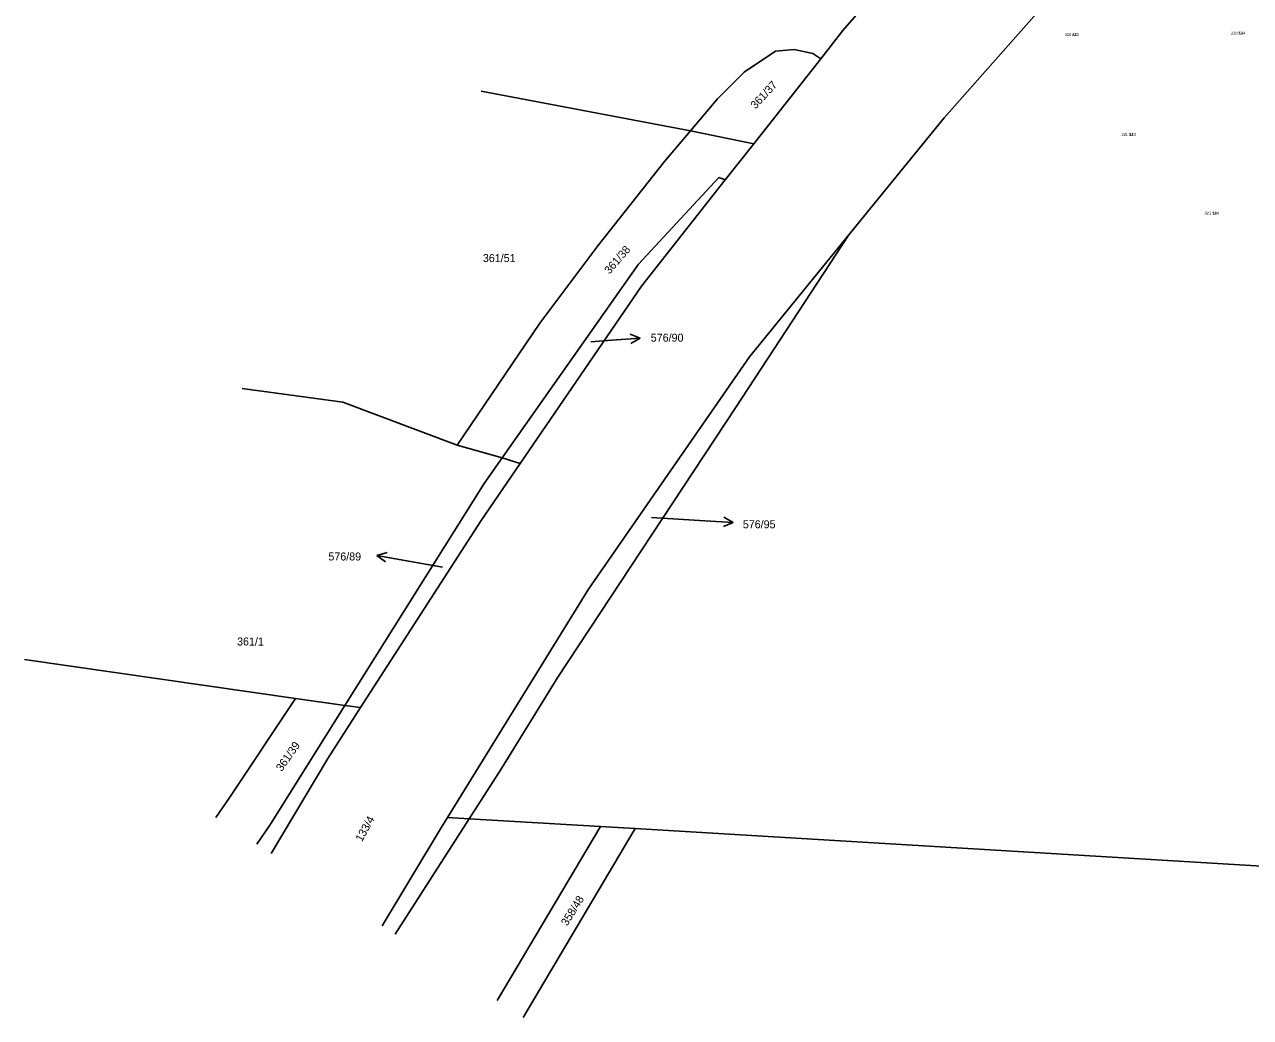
# Model space of a CAD drawing. Extents: x -742884 to -742543, y -1054677 to -1054433.
# Drawn here: x -742884.1 to -742753.9, y -1054651.8 to -1054546.4 of the extents above; entities that cross this region are included whole.
import ezdxf

# ---------------------------------------------------------------- set-up
doc = ezdxf.new("R2010")
doc.units = 0
for name, color, linetype in [('Vrstva 1', 7, 'Continuous'), ('Vrstva 11', 7, 'Continuous'), ('Vrstva 2', 7, 'Continuous'), ('Vrstva 3', 7, 'Continuous'), ('Vrstva 50', 7, 'Continuous')]:
    doc.layers.add(name, color=color, linetype=linetype)

msp = doc.modelspace()

# ---------------------------------------------------------------- linework, layer by layer
at = {"layer": 'Vrstva 1'}
for p, q in [((-742772.8, -1054547.58), (-742772.8, -1054547.58)), ((-742755.15, -1054547.44), (-742755.15, -1054547.44)), ((-742766.77, -1054558.2), (-742766.77, -1054558.2)), ((-742757.95, -1054566.55), (-742757.95, -1054566.55))]:
    msp.add_line(p, q, dxfattribs=at)
at = {"layer": 'Vrstva 11'}
msp.add_spline([(-742641.45, -1054542), (-742646.08, -1054542.32), (-742650.28, -1054545.1), (-742653.63, -1054549.14), (-742658.66, -1054557.13), (-742664.13, -1054565.84), (-742667.81, -1054569.62), (-742669.76, -1054570.07), (-742674.4, -1054567.88), (-742684.66, -1054562.03), (-742693.02, -1054556.88), (-742694.43, -1054554.37), (-742693.99, -1054552.67), (-742684.52, -1054539.64), (-742677.51, -1054529.95), (-742676.26, -1054526.54), (-742677.27, -1054522.39), (-742681.19, -1054517.29), (-742689.28, -1054510.73), (-742697.86, -1054505.14), (-742704.02, -1054502.75), (-742713.11, -1054501.07), (-742723.98, -1054503.51), (-742736.77, -1054510.1), (-742745.39, -1054515.75), (-742752.81, -1054521.82), (-742762.72, -1054531.38), (-742770.54, -1054539.36), (-742775.54, -1054544.64)], degree=3, dxfattribs=at)
at = {"layer": 'Vrstva 50'}
for p, q in [((-742806.65, -1054559.03), (-742799.53, -1054550)), ((-742810.52, -1054554.25), (-742813.37, -1054557.65)), ((-742813.37, -1054557.65), (-742816.15, -1054560.93)), ((-742813.37, -1054557.65), (-742806.65, -1054559.03)), ((-742809.68, -1054562.87), (-742806.65, -1054559.03)), ((-742829.38, -1054578.09), (-742838.16, -1054591.04)), ((-742821.73, -1054579.9), (-742818.74, -1054579.69)), ((-742818.74, -1054579.69), (-742819.77, -1054579.26)), ((-742818.74, -1054579.69), (-742819.7, -1054580.26)), ((-742823.97, -1054580.07), (-742821.73, -1054579.9)), ((-742833.37, -1054592.38), (-742838.16, -1054591.04)), ((-742831.46, -1054592.98), (-742833.37, -1054592.38)), ((-742817.51, -1054598.74), (-742811.86, -1054599.08)), ((-742811.86, -1054599.08), (-742808.86, -1054599.24)), ((-742808.86, -1054599.24), (-742809.89, -1054599.69)), ((-742808.86, -1054599.24), (-742809.84, -1054598.69)), ((-742846.68, -1054602.77), (-742845.6, -1054602.45)), ((-742843.72, -1054603.29), (-742846.68, -1054602.77)), ((-742846.68, -1054602.77), (-742845.78, -1054603.44)), ((-742839.71, -1054603.99), (-742843.72, -1054603.29)), ((-742855.32, -1054617.94), (-742850.08, -1054618.69)), ((-742848.43, -1054618.92), (-742850.08, -1054618.69)), ((-742839.19, -1054630.57), (-742836.88, -1054630.71)), ((-742822.95, -1054631.55), (-742836.88, -1054630.71)), ((-742833.92, -1054650.02), (-742822.95, -1054631.55)), ((-742819.25, -1054631.77), (-742831.15, -1054651.82)), ((-742819.25, -1054631.77), (-742822.95, -1054631.55)), ((-742684.03, -1054639.89), (-742819.25, -1054631.77))]:
    msp.add_line(p, q, dxfattribs=at)
for points in [[(-742724.95, -1054484.46), (-742747.39, -1054511.11), (-742766.3, -1054533.47), (-742786.45, -1054556.28), (-742796.57, -1054568.72)], [(-742799.53, -1054550), (-742797.18, -1054547.02), (-742783.25, -1054530.97)], [(-742799.53, -1054550), (-742800.38, -1054549.44), (-742802.37, -1054549.04), (-742804.34, -1054549.2), (-742807.67, -1054551.44), (-742810.52, -1054554.25)], [(-742813.37, -1054557.65), (-742835.62, -1054553.44)], [(-742816.15, -1054560.93), (-742823.22, -1054569.87), (-742829.38, -1054578.09)], [(-742833.37, -1054592.38), (-742818.9, -1054571.81), (-742810.36, -1054562.62), (-742809.68, -1054562.87)], [(-742831.46, -1054592.98), (-742818.59, -1054574.17), (-742809.68, -1054562.87)], [(-742796.57, -1054568.72), (-742807.1, -1054581.66), (-742824.22, -1054606.33), (-742839.19, -1054630.57)], [(-742796.57, -1054568.72), (-742808.61, -1054587.07), (-742827.46, -1054615.67), (-742833.45, -1054625.38), (-742836.88, -1054630.71)], [(-742838.16, -1054591.04), (-742850.31, -1054586.48), (-742860.99, -1054585.01)], [(-742850.08, -1054618.69), (-742835.29, -1054595.11), (-742833.37, -1054592.38)], [(-742848.43, -1054618.92), (-742835.61, -1054599.05), (-742831.46, -1054592.98)], [(-742884.11, -1054613.8), (-742855.32, -1054617.94)], [(-742855.32, -1054617.94), (-742862.37, -1054628.54), (-742863.78, -1054630.58)], [(-742859.44, -1054633.41), (-742858, -1054631.31), (-742850.08, -1054618.69)], [(-742857.9, -1054634.41), (-742851.91, -1054624.32), (-742848.43, -1054618.92)], [(-742839.19, -1054630.57), (-742839.94, -1054631.78), (-742846.11, -1054642.09)], [(-742836.88, -1054630.71), (-742844.76, -1054642.97)]]:
    msp.add_lwpolyline(points, dxfattribs=at)

# ---------------------------------------------------------------- texts
at = {"layer": 'Vrstva 2'}
for s, p in [('143', (-742772.8, -1054547.58)), ('134', (-742755.15, -1054547.44)), ('133', (-742766.77, -1054558.2)), ('144', (-742757.95, -1054566.55))]:
    msp.add_text(s, height=0.3, dxfattribs=at).set_placement(p)
at = {"layer": 'Vrstva 3'}
for s, p in [('320 81 ', (-742773.63, -1054547.58)), ('320 59 ', (-742755.98, -1054547.44)), ('321 04 ', (-742767.6, -1054558.2)), ('321 12 ', (-742758.78, -1054566.55))]:
    msp.add_text(s, height=0.3, dxfattribs=at).set_placement(p)
at = {"layer": 'Vrstva 50'}
for s, rotation, p in [('361/37', 47, (-742806.47, -1054555.4)), ('361/38', 49, (-742821.98, -1054572.94)), ('361/39', 55, (-742856.79, -1054625.76)), ('133/4', 61, (-742848.28, -1054633.23)), ('358/48', 58, (-742826.48, -1054642.17))]:
    msp.add_text(s, height=0.85, rotation=rotation, dxfattribs=at).set_placement(p)
for s, p in [('361/51', (-742835.43, -1054571.6)), ('576/90', (-742817.6, -1054580.05)), ('576/95', (-742807.82, -1054599.87)), ('576/89', (-742851.84, -1054603.29)), ('361/1', (-742861.54, -1054612.32))]:
    msp.add_text(s, height=0.85, dxfattribs=at).set_placement(p)

doc.saveas('drawing.dxf')
